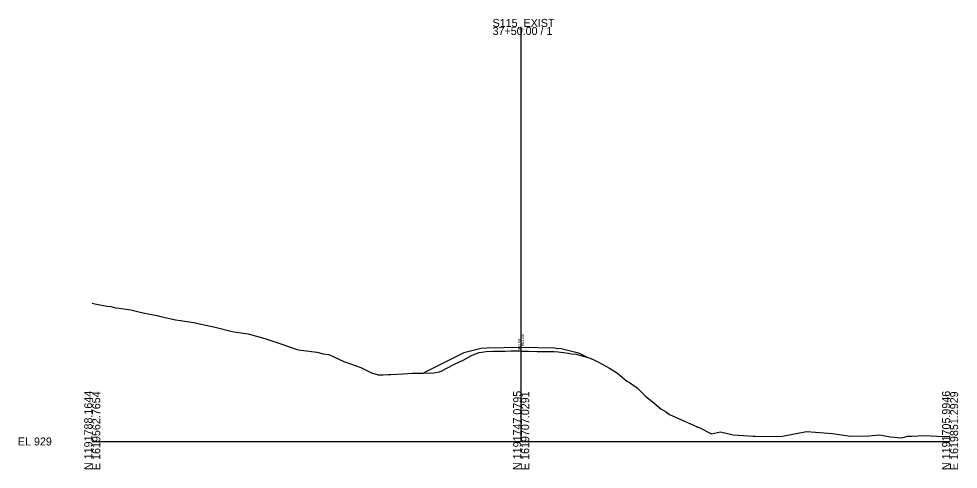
# Model space of a CAD drawing. Extents: x 1620351 to 1620680, y 1192592 to 1195749.
# Drawn here: x 1620351.1 to 1620679.6, y 1194091.8 to 1194249.1 of the extents above; entities that cross this region are included whole.
import ezdxf

# ---------------------------------------------------------------- set-up
doc = ezdxf.new("R2010")
doc.units = 0
for name, color, linetype in [('RD_GPK_XS_Cell', 7, 'Continuous'), ('RD_XS_EarthShd', 7, 'Continuous'), ('RD_XS_ExGround', 7, 'Continuous'), ('RD_XS_Pave', 7, 'Continuous'), ('RD_XS_TieSlope', 7, 'Continuous'), ('RD_XS_TX_Elev_EX', 7, 'Continuous'), ('RD_XS_TX_Elev_PR', 7, 'Continuous')]:
    doc.layers.add(name, color=color, linetype=linetype)

msp = doc.modelspace()

# ---------------------------------------------------------------- linework, layer by layer
at = {"layer": 'RD_GPK_XS_Cell'}
for p, q in [((1620526.76, 1194101.47), (1620526.76, 1194246.27)), ((1620376.76, 1194101.47), (1620526.76, 1194101.47)), ((1620526.76, 1194101.47), (1620676.76, 1194101.47))]:
    msp.add_line(p, q, dxfattribs=at)
at = {"layer": 'RD_XS_EarthShd'}
for p, q in [((1620514.76, 1194134.08), (1620512.76, 1194133.92)), ((1620538.76, 1194134.08), (1620540.76, 1194133.92))]:
    msp.add_line(p, q, dxfattribs=at)
at = {"layer": 'RD_XS_ExGround'}
msp.add_lwpolyline([(1620376.76, 1194149.73), (1620377.66, 1194149.58), (1620381.87, 1194148.77), (1620383.2, 1194148.55), (1620385.04, 1194148.19), (1620386.15, 1194147.98), (1620390.25, 1194147.39), (1620393.51, 1194146.64), (1620395.2, 1194146.22), (1620395.68, 1194146.12), (1620399.29, 1194145.42), (1620399.94, 1194145.29), (1620400.28, 1194145.22), (1620405.88, 1194144), (1620407.6, 1194143.75), (1620412.34, 1194142.96), (1620413.17, 1194142.8), (1620419.7, 1194141.37), (1620425.74, 1194139.92), (1620426.44, 1194139.77), (1620431.32, 1194139.07), (1620437.17, 1194137.46), (1620438.21, 1194137.12), (1620442.35, 1194135.72), (1620448.05, 1194133.75), (1620448.87, 1194133.47), (1620449.84, 1194133.36), (1620455.27, 1194132.7), (1620457.53, 1194132.06), (1620459.44, 1194131.79), (1620464.77, 1194129.38), (1620470.7, 1194127.35), (1620474.45, 1194125.48), (1620476.78, 1194124.73), (1620478.5, 1194124.77), (1620480.37, 1194124.87), (1620481.22, 1194124.89), (1620485.37, 1194125.06), (1620487.17, 1194125.21), (1620488.74, 1194125.32), (1620489.23, 1194125.27), (1620492.48, 1194125.37), (1620493.3, 1194125.39), (1620494.64, 1194125.27), (1620496.21, 1194125.43), (1620498.15, 1194125.74), (1620498.96, 1194126.09), (1620500.34, 1194126.85), (1620503.64, 1194128.54), (1620506.45, 1194129.83), (1620509.66, 1194131.55), (1620512.05, 1194132.56), (1620513.04, 1194132.67), (1620514.53, 1194132.88), (1620516.91, 1194132.96), (1620518.41, 1194133), (1620521.11, 1194133.03), (1620523.15, 1194133.1), (1620524.84, 1194133.09), (1620525.48, 1194133.08), (1620526.76, 1194133.04), (1620529.45, 1194132.96), (1620532.31, 1194132.89), (1620533.3, 1194132.88), (1620537.32, 1194132.87), (1620538.25, 1194132.85), (1620539.68, 1194132.75), (1620541.62, 1194132.49), (1620543.29, 1194132.25), (1620544.26, 1194132.1), (1620546.03, 1194131.91), (1620550.88, 1194130.59), (1620552.13, 1194129.98), (1620553.75, 1194129.2), (1620557.62, 1194127.1), (1620560.44, 1194125.31), (1620563.7, 1194122.57), (1620564.66, 1194122.06), (1620567.34, 1194120.23), (1620570.28, 1194117.34), (1620573.3, 1194114.82), (1620575.63, 1194112.9), (1620577.19, 1194111.9), (1620578.67, 1194110.84), (1620580.74, 1194109.9), (1620588.05, 1194106.68), (1620588.44, 1194106.49), (1620588.82, 1194106.42), (1620593.27, 1194104.16), (1620596.46, 1194104.82), (1620600.86, 1194103.82), (1620606.26, 1194103.39), (1620607.9, 1194103.35), (1620608.61, 1194103.29), (1620616.47, 1194103.24), (1620618.14, 1194103.32), (1620626.52, 1194104.91), (1620629.67, 1194104.75), (1620635.68, 1194104.21), (1620641.9, 1194103.33), (1620648.41, 1194103.39), (1620652.12, 1194103.73), (1620655.81, 1194103.05), (1620659.9, 1194102.74), (1620661.91, 1194103.31), (1620663.44, 1194103.33), (1620667.58, 1194103.58), (1620674.84, 1194103.23), (1620676.45, 1194103.26), (1620676.76, 1194103.29)], dxfattribs=at)
at = {"layer": 'RD_XS_Pave'}
for p, q in [((1620526.76, 1194134.32), (1620514.76, 1194134.08)), ((1620538.76, 1194134.08), (1620526.76, 1194134.32))]:
    msp.add_line(p, q, dxfattribs=at)
at = {"layer": 'RD_XS_TieSlope'}
for p, q in [((1620512.76, 1194133.92), (1620506.76, 1194132.42)), ((1620540.76, 1194133.92), (1620546.76, 1194132.42)), ((1620506.76, 1194132.42), (1620492.69, 1194125.38)), ((1620546.76, 1194132.42), (1620549.85, 1194130.87))]:
    msp.add_line(p, q, dxfattribs=at)

# ---------------------------------------------------------------- texts
at = {"layer": 'RD_GPK_XS_Cell'}
for s, p in [('S115_EXIST', (1620516.76, 1194246.27)), ('37+50.00 / 1', (1620516.76, 1194243.47)), ('EL 929', (1620350.76, 1194100.07))]:
    msp.add_text(s, height=2.8, dxfattribs=at).set_placement(p)
for s, p in [('N 1191788.1644', (1620376.76, 1194091.47)), ('E 1619562.7654', (1620379.56, 1194091.47)), ('N 1191747.0795', (1620526.76, 1194091.47)), ('E 1619707.0291', (1620529.56, 1194091.47)), ('N 1191705.9946', (1620676.76, 1194091.47)), ('E 1619851.2929', (1620679.56, 1194091.47))]:
    msp.add_text(s, height=2.8, rotation=90, dxfattribs=at).set_placement(p)
at = {"layer": 'RD_XS_TX_Elev_EX'}
msp.add_text('960.58', height=1, rotation=90, dxfattribs=at).set_placement((1620526.66, 1194133.14))
at = {"layer": 'RD_XS_TX_Elev_PR'}
msp.add_text(' 961.85', height=1, rotation=90, dxfattribs=at).set_placement((1620527.76, 1194134.32))

doc.saveas('drawing.dxf')
